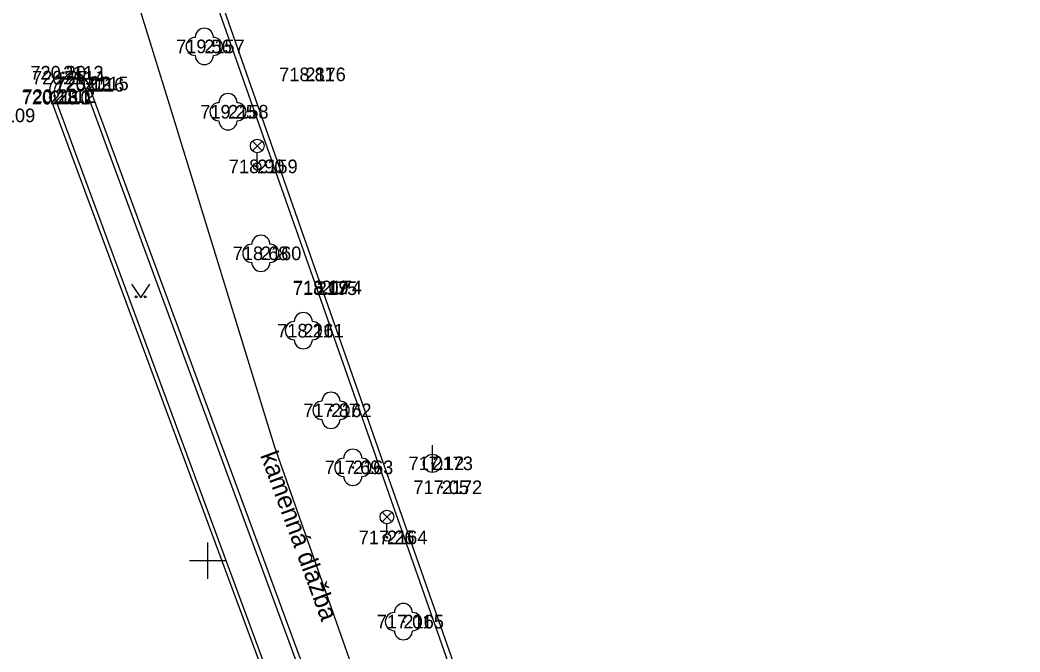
# Model space of a CAD drawing. Extents: x -844765 to -843273, y -997542 to -995529.
# Drawn here: x -844610.3 to -844555.2, y -995955 to -995920.2 of the extents above; entities that cross this region are included whole.
import ezdxf

# ---------------------------------------------------------------- set-up
doc = ezdxf.new("R2010")
doc.units = 0
for name, color, linetype in [('Betonový strop', 7, 'Continuous'), ('Dno', 7, 'Continuous'), ('Doplněk polohopisu', 7, 'Continuous'), ('Groma', 7, 'Continuous'), ('Osa', 7, 'Continuous'), ('Rámeček', 7, 'Continuous'), ('Sítě podzemní nerozlišené', 7, 'Continuous'), ('Výška', 7, 'Continuous'), ('Výškopis', 7, 'Continuous'), ('Číslo bodu', 7, 'Continuous'), ('Řezy', 7, 'Continuous')]:
    doc.layers.add(name, color=color, linetype=linetype)

msp = doc.modelspace()

# ---------------------------------------------------------------- linework, layer by layer
at = {"layer": 'Betonový strop'}
for points in [[(-844629.12, -995861.21), (-844625.65, -995859.15), (-844621.49, -995856.6), (-844620.48, -995855.21), (-844619.24, -995854.94), (-844616.52, -995865.52), (-844610.55, -995885.46), (-844605.08, -995902.6), (-844600.8, -995914.77), (-844593.72, -995934.94), (-844584.42, -995961.39), (-844579.21, -995976.3)], [(-844579.45, -995976.35), (-844584.66, -995961.49), (-844593.98, -995934.98), (-844601.34, -995914.07), (-844605.29, -995902.68), (-844610.78, -995885.51), (-844616.77, -995865.64), (-844619.45, -995855.22), (-844620.38, -995855.56), (-844621.35, -995856.86), (-844628.99, -995861.43)], [(-844606.82, -995923.77), (-844594.15, -995958.14), (-844587.87, -995975.01)], [(-844587.66, -995974.93), (-844593.61, -995958.84), (-844606.58, -995923.7)], [(-844608.68, -995924.48), (-844595.8, -995959.22), (-844589.72, -995975.76)], [(-844589.47, -995975.69), (-844595.77, -995958.64), (-844608.43, -995924.4)]]:
    msp.add_lwpolyline(points, dxfattribs=at)
for centre, radius, start, end in [((-844607.599, -995924.174), 1.124, 24.952, 195.8008), ((-844607.583, -995924.192), 0.872, 28.9722, 193.7691)]:
    msp.add_arc(centre, radius, start, end, dxfattribs=at)
at = {"layer": 'Dno'}
msp.add_lwpolyline([(-844604.185, -995934.753), (-844603.685, -995935.503), (-844603.185, -995934.753)], dxfattribs=at)
for centre in [(-844603.935, -995935.453), (-844603.435, -995935.453)]:
    msp.add_circle(centre, 0.05, dxfattribs=at)
at = {"layer": 'Doplněk polohopisu'}
msp.add_line((-844587.6, -995945.13), (-844587.6, -995943.63), dxfattribs=at)
msp.add_circle((-844587.6, -995944.63), 0.5, dxfattribs=at)
at = {"layer": 'Groma'}
for p, q in [((-844597.524, -995927.408), (-844596.996, -995926.88)), ((-844596.988, -995927.405), (-844597.516, -995926.876)), ((-844597.26, -995928.07), (-844597.26, -995927.52)), ((-844590.374, -995947.848), (-844589.846, -995947.32)), ((-844589.838, -995947.845), (-844590.366, -995947.316)), ((-844590.11, -995948.51), (-844590.11, -995947.96))]:
    msp.add_line(p, q, dxfattribs=at)
for centre, radius in [((-844597.26, -995927.145), 0.375), ((-844597.26, -995928.27), 0.2), ((-844590.11, -995947.585), 0.375), ((-844590.11, -995948.71), 0.2)]:
    msp.add_circle(centre, radius, dxfattribs=at)
at = {"layer": 'Osa'}
msp.add_lwpolyline([(-844555.208, -996045.307), (-844559.6, -996036.37), (-844563.495, -996027.16), (-844571.238, -996008.81), (-844575.085, -995999.67), (-844582.535, -995981.015), (-844589.66, -995962.57), (-844596.305, -995943.685), (-844602.165, -995924.63), (-844608.085, -995905.52), (-844613.78, -995886.51), (-844619.57, -995867.42), (-844624.395, -995848.01), (-844628.94, -995828.61), (-844632.81, -995809.025), (-844636.18, -995789.375)], dxfattribs=at)
at = {"layer": 'Rámeček'}
for p, q in [((-844600, -995949), (-844600, -995951)), ((-844599, -995950), (-844601, -995950))]:
    msp.add_line(p, q, dxfattribs=at)
at = {"layer": 'Sítě podzemní nerozlišené'}
for p, q in [((-844600.18, -995921.66), (-844600.23, -995921.61)), ((-844600.18, -995921.66), (-844600.23, -995921.71)), ((-844600.18, -995921.66), (-844600.13, -995921.61)), ((-844600.18, -995921.66), (-844600.13, -995921.71)), ((-844607.96, -995923.11), (-844608.01, -995923.06)), ((-844607.96, -995923.11), (-844608.01, -995923.16)), ((-844607.96, -995923.11), (-844607.91, -995923.06)), ((-844607.96, -995923.11), (-844607.91, -995923.16)), ((-844594.61, -995923.2), (-844594.66, -995923.15)), ((-844594.61, -995923.2), (-844594.66, -995923.25)), ((-844594.61, -995923.2), (-844594.56, -995923.15)), ((-844594.61, -995923.2), (-844594.56, -995923.25)), ((-844607.9, -995923.38), (-844607.95, -995923.33)), ((-844607.9, -995923.38), (-844607.95, -995923.43)), ((-844607.9, -995923.38), (-844607.85, -995923.33)), ((-844607.9, -995923.38), (-844607.85, -995923.43)), ((-844606.82, -995923.77), (-844606.87, -995923.72)), ((-844606.82, -995923.77), (-844606.87, -995923.82)), ((-844606.82, -995923.77), (-844606.77, -995923.72)), ((-844606.82, -995923.77), (-844606.77, -995923.82)), ((-844606.58, -995923.7), (-844606.63, -995923.65)), ((-844606.58, -995923.7), (-844606.63, -995923.75)), ((-844606.58, -995923.7), (-844606.53, -995923.65)), ((-844606.58, -995923.7), (-844606.53, -995923.75)), ((-844608.43, -995924.4), (-844608.48, -995924.35)), ((-844608.43, -995924.4), (-844608.38, -995924.35)), ((-844608.68, -995924.47), (-844608.73, -995924.42)), ((-844608.68, -995924.48), (-844608.73, -995924.43)), ((-844608.68, -995924.47), (-844608.73, -995924.52)), ((-844608.68, -995924.48), (-844608.73, -995924.53)), ((-844608.68, -995924.47), (-844608.63, -995924.42)), ((-844608.68, -995924.48), (-844608.63, -995924.43)), ((-844608.68, -995924.47), (-844608.63, -995924.52)), ((-844608.68, -995924.48), (-844608.63, -995924.53)), ((-844608.43, -995924.4), (-844608.48, -995924.45)), ((-844608.43, -995924.4), (-844608.38, -995924.45)), ((-844598.87, -995925.26), (-844598.92, -995925.21)), ((-844598.87, -995925.26), (-844598.92, -995925.31)), ((-844598.87, -995925.26), (-844598.82, -995925.21)), ((-844598.87, -995925.26), (-844598.82, -995925.31)), ((-844597.26, -995928.27), (-844597.31, -995928.22)), ((-844597.26, -995928.27), (-844597.21, -995928.22)), ((-844597.26, -995928.27), (-844597.31, -995928.32)), ((-844597.26, -995928.27), (-844597.21, -995928.32)), ((-844597.06, -995933.06), (-844597.11, -995933.01)), ((-844597.06, -995933.06), (-844597.11, -995933.11)), ((-844597.06, -995933.06), (-844597.01, -995933.01)), ((-844597.06, -995933.06), (-844597.01, -995933.11)), ((-844593.98, -995934.98), (-844594.03, -995934.93)), ((-844593.98, -995934.98), (-844594.03, -995935.03)), ((-844593.98, -995934.98), (-844593.93, -995934.93)), ((-844593.98, -995934.98), (-844593.93, -995935.03)), ((-844593.72, -995934.94), (-844593.77, -995934.89)), ((-844593.72, -995934.94), (-844593.77, -995934.99)), ((-844593.72, -995934.94), (-844593.67, -995934.89)), ((-844593.72, -995934.94), (-844593.67, -995934.99)), ((-844594.72, -995937.32), (-844594.77, -995937.27)), ((-844594.72, -995937.32), (-844594.77, -995937.37)), ((-844594.72, -995937.32), (-844594.67, -995937.27)), ((-844594.72, -995937.32), (-844594.67, -995937.37)), ((-844593.19, -995941.71), (-844593.24, -995941.66)), ((-844593.19, -995941.71), (-844593.24, -995941.76)), ((-844593.19, -995941.71), (-844593.14, -995941.66)), ((-844593.19, -995941.71), (-844593.14, -995941.76)), ((-844587.6, -995944.63), (-844587.65, -995944.58)), ((-844587.6, -995944.63), (-844587.65, -995944.68)), ((-844587.6, -995944.63), (-844587.55, -995944.58)), ((-844587.6, -995944.63), (-844587.55, -995944.68)), ((-844591.99, -995944.85), (-844592.04, -995944.8)), ((-844591.99, -995944.85), (-844592.04, -995944.9)), ((-844591.99, -995944.85), (-844591.94, -995944.8)), ((-844591.99, -995944.85), (-844591.94, -995944.9)), ((-844587.09, -995945.95), (-844587.14, -995945.9)), ((-844587.09, -995945.95), (-844587.14, -995946)), ((-844587.09, -995945.95), (-844587.04, -995945.9)), ((-844587.09, -995945.95), (-844587.04, -995946)), ((-844590.11, -995948.71), (-844590.16, -995948.66)), ((-844590.11, -995948.71), (-844590.16, -995948.76)), ((-844590.11, -995948.71), (-844590.06, -995948.66)), ((-844590.11, -995948.71), (-844590.06, -995948.76)), ((-844589.2, -995953.35), (-844589.25, -995953.3)), ((-844589.2, -995953.35), (-844589.25, -995953.4)), ((-844589.2, -995953.35), (-844589.15, -995953.3)), ((-844589.2, -995953.35), (-844589.15, -995953.4))]:
    msp.add_line(p, q, dxfattribs=at)
at = {"layer": 'Výškopis'}
for centre in [(-844600.18, -995921.66), (-844598.87, -995925.26), (-844597.06, -995933.06), (-844594.72, -995937.32), (-844593.19, -995941.71), (-844591.99, -995944.85), (-844589.2, -995953.35)]:
    msp.add_circle(centre, 0.0005, dxfattribs=at)
for centre, start, end in [((-844600.18, -995921.16), 0, 180), ((-844600.68, -995921.66), 90, 270), ((-844599.68, -995921.66), 270, 90), ((-844600.18, -995922.16), 180, 360), ((-844598.87, -995924.76), 0, 180), ((-844599.37, -995925.26), 90, 270), ((-844598.37, -995925.26), 270, 90), ((-844598.87, -995925.76), 180, 360), ((-844597.06, -995932.56), 0, 180), ((-844597.56, -995933.06), 90, 270), ((-844596.56, -995933.06), 270, 90), ((-844597.06, -995933.56), 180, 360), ((-844594.72, -995936.82), 0, 180), ((-844595.22, -995937.32), 90, 270), ((-844594.22, -995937.32), 270, 90), ((-844594.72, -995937.82), 180, 360), ((-844593.19, -995941.21), 0, 180), ((-844593.69, -995941.71), 90, 270), ((-844592.69, -995941.71), 270, 90), ((-844593.19, -995942.21), 180, 360), ((-844591.99, -995944.35), 0, 180), ((-844592.49, -995944.85), 90, 270), ((-844591.49, -995944.85), 270, 90), ((-844591.99, -995945.35), 180, 360), ((-844589.2, -995952.85), 0, 180), ((-844589.7, -995953.35), 90, 270), ((-844588.7, -995953.35), 270, 90), ((-844589.2, -995953.85), 180, 360)]:
    msp.add_arc(centre, 0.5, start, end, dxfattribs=at)

# ---------------------------------------------------------------- texts
at = {"layer": 'Výška'}
msp.add_text('kamenná dlažba', height=1, rotation=290.2589, dxfattribs=at).set_placement((-844597.108, -995944.184))
at = {"layer": 'Číslo bodu'}
for s, p in [('2157', (-844600.18, -995922.035)), ('2113', (-844607.96, -995923.485)), ('2114', (-844607.9, -995923.755)), ('2176', (-844594.61, -995923.575)), ('2116', (-844606.82, -995924.145)), ('2115', (-844606.58, -995924.075)), ('2111', (-844608.68, -995924.845)), ('2110', (-844608.68, -995924.855)), ('2112', (-844608.43, -995924.775)), ('2158', (-844598.87, -995925.635)), ('2109', (-844611.73, -995925.835)), ('2159', (-844597.26, -995928.645)), ('2160', (-844597.06, -995933.435)), ('2175', (-844593.98, -995935.355)), ('2174', (-844593.72, -995935.315)), ('2161', (-844594.72, -995937.695)), ('2162', (-844593.19, -995942.085)), ('2163', (-844591.99, -995945.225)), ('2173', (-844587.6, -995945.005)), ('2172', (-844587.09, -995946.325)), ('2164', (-844590.11, -995949.085)), ('2165', (-844589.2, -995953.725))]:
    msp.add_text(s, height=0.75, dxfattribs=at).set_placement(p)
at = {"layer": 'Řezy'}
for s, p in [('719.56', (-844601.733, -995922.035)), ('720.20', (-844609.767, -995923.485)), ('720.27', (-844609.674, -995923.755)), ('718.81', (-844596.051, -995923.575)), ('720.02', (-844608.387, -995924.075)), ('720.13', (-844608.382, -995924.145)), ('720.18', (-844610.242, -995924.845)), ('720.18', (-844610.242, -995924.855)), ('720.23', (-844610.204, -995924.775)), ('719.25', (-844600.402, -995925.635)), ('718.90', (-844598.825, -995928.645)), ('718.68', (-844598.61, -995933.435)), ('718.17', (-844595.297, -995935.355)), ('718.09', (-844595.285, -995935.315)), ('718.21', (-844596.161, -995937.695)), ('717.87', (-844594.719, -995942.085)), ('717.69', (-844593.543, -995945.225)), ('717.12', (-844588.917, -995945.005)), ('717.05', (-844588.652, -995946.325)), ('717.26', (-844591.66, -995949.085)), ('717.01', (-844590.673, -995953.725))]:
    msp.add_text(s, height=0.75, dxfattribs=at).set_placement(p)

doc.saveas('drawing.dxf')
